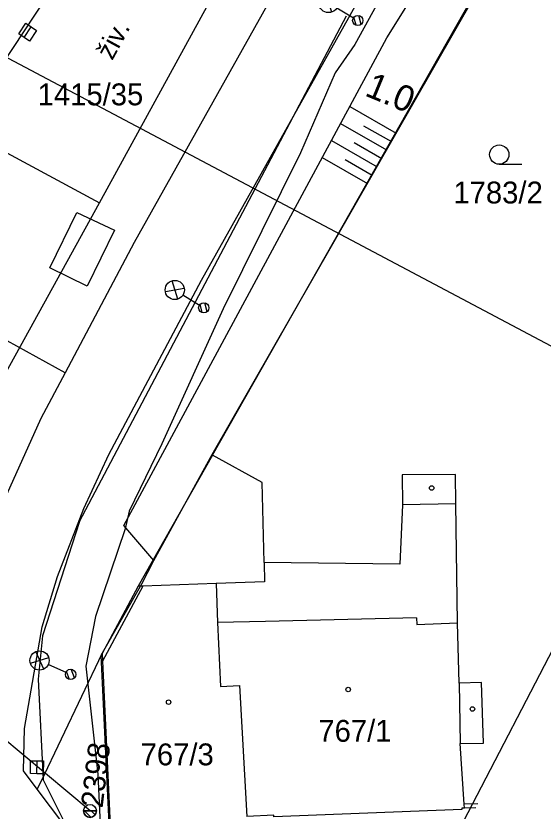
# Model space of a CAD drawing. Extents: x -781083 to -763634, y -1029516 to -1022695.
# Drawn here: x -765189.4 to -765148.4, y -1024336.1 to -1024274.3 of the extents above; entities that cross this region are included whole.
import ezdxf

# ---------------------------------------------------------------- set-up
doc = ezdxf.new("R2010")
doc.units = 0
for name, color, linetype in [('CETIN_nezaměřený', 7, 'Continuous'), ('Hranice parcel', 7, 'Continuous'), ('Parcelní čísla', 7, 'Continuous'), ('Vnitřní kresba', 7, 'Continuous'), ('Vrstva 16', 7, 'Continuous'), ('Vrstva 17', 7, 'Continuous'), ('Vrstva 23', 7, 'Continuous'), ('Vrstva 25', 7, 'Continuous'), ('Vrstva 36', 7, 'Continuous'), ('Vrstva 43', 7, 'Continuous'), ('Vrstva 48', 7, 'Continuous'), ('Vrstva 49', 7, 'Continuous'), ('Vrstva 5', 7, 'Continuous'), ('Vrstva 51', 7, 'Continuous'), ('Značky budov', 7, 'Continuous'), ('Značky kultur', 7, 'Continuous')]:
    doc.layers.add(name, color=color, linetype=linetype)

# ---------------------------------------------------------------- blocks, each defined once
blk = doc.blocks.new('4.02')
at = {"layer": 'Značky budov'}
blk.add_circle((-0.07, 0.01), 1.75, dxfattribs=at)
blk = doc.blocks.new('3.04')
at = {"layer": 'Značky kultur'}
blk.add_line((0.07, 0), (17.57, 0), dxfattribs=at)
blk.add_circle((0.07, 7.5), 7.5, dxfattribs=at)
blk = doc.blocks.new('C187_11')
at = {"layer": 'Vrstva 25'}
for p, q in [((-4.94, 32.07), (5, 20.95)), ((-4.79, 20.77), (5.05, 31.98)), ((0, 19), (0, 4)), ((-3.89, -0.8), (0.8, 3.89)), ((-1.21, -3.77), (3.79, 1.23))]:
    blk.add_line(p, q, dxfattribs=at)
for centre, radius in [((-0.03, 26.48), 7.49), ((0, 0), 4), ((0, 0), 4)]:
    blk.add_circle(centre, radius, dxfattribs=at)
blk = doc.blocks.new('C187_17')
at = {"layer": 'Vrstva 25'}
for p, q in [((-4.94, 32.07), (5, 20.95)), ((-4.79, 20.77), (5.05, 31.98)), ((0, 19), (0, 4)), ((-3.89, -0.8), (0.8, 3.89)), ((-1.21, -3.77), (3.79, 1.23))]:
    blk.add_line(p, q, dxfattribs=at)
for centre, radius in [((-0.03, 26.48), 7.49), ((0, 0), 4), ((0, 0), 4)]:
    blk.add_circle(centre, radius, dxfattribs=at)
blk = doc.blocks.new('C187_8')
at = {"layer": 'Vrstva 25'}
for p, q in [((-4.94, 32.07), (5, 20.95)), ((-4.79, 20.77), (5.05, 31.98)), ((0, 19), (0, 4)), ((-3.89, -0.8), (0.8, 3.89)), ((-1.21, -3.77), (3.79, 1.23))]:
    blk.add_line(p, q, dxfattribs=at)
for centre, radius in [((-0.03, 26.49), 7.49), ((0, 0), 4), ((0, 0), 4)]:
    blk.add_circle(centre, radius, dxfattribs=at)
blk = doc.blocks.new('C724_9')
at = {"layer": 'Vrstva 36'}
for p, q in [((-5.03, 0), (5.03, 0)), ((5.03, 0), (-5.03, 0)), ((0.63, -4.98), (-4.34, 0)), ((3.98, -3.02), (0.96, 0))]:
    blk.add_line(p, q, dxfattribs=at)
blk.add_lwpolyline([(-5.03, 0), (5.03, 0)], dxfattribs=at)
blk.add_circle((0, 0), 5.03, dxfattribs=at)
blk.add_arc((0, 0), 5.03, 180, 0, dxfattribs=at)
blk.add_arc((0, 0), 5.03, 180, 0, dxfattribs=at)
blk = doc.blocks.new('C154_1')
at = {"layer": 'Vrstva 43'}
blk.add_lwpolyline([(-5, 0), (-5, 5), (5, 5), (5, -5), (-5, -5), (-5, 0), (5, 0)], dxfattribs=at)

msp = doc.modelspace()

# ---------------------------------------------------------------- linework, layer by layer
msp.add_lwpolyline([(-765336.117, -1024363.479), (-765204.05, -1024432.093), (-764769.725, -1023596.107), (-764901.792, -1023527.494)], close=True)
at = {"layer": 'CETIN_nezaměřený'}
msp.add_lwpolyline([(-765156.32, -1024264.33), (-765163.03, -1024276.53), (-765164.57, -1024278.73), (-765167.26, -1024284.94), (-765173.26, -1024297.07), (-765178.03, -1024307.57), (-765180.58, -1024312.81), (-765180.89, -1024314.18), (-765183.19, -1024320.98), (-765183.94, -1024324.85), (-765183.02, -1024333.24), (-765182.82, -1024337.72)], dxfattribs=at)
at = {"layer": 'Hranice parcel'}
for p, q in [((-765174.11, -1024308.46), (-765144.5, -1024256.37)), ((-765185.57, -1024302.05), (-765199.67, -1024294.27)), ((-765185.67, -1024337.15), (-765187.73, -1024334.42)), ((-765153.624, -1024335.86), (-765154.51, -1024335.89))]:
    msp.add_line(p, q, dxfattribs=at)
for points in [[(-765187.73, -1024334.42), (-765188.8, -1024333), (-765188.73, -1024329.7), (-765187.34, -1024321.79), (-765186.15, -1024317.88), (-765184.1, -1024312.59), (-765182.16, -1024308.4), (-765174.96, -1024294.85), (-765154.33, -1024258.05), (-765087.21, -1024139.28), (-765076.299, -1024121.401)], [(-765155.36, -1024247.61), (-765159.55, -1024255.1), (-765180.19, -1024291.92), (-765185.57, -1024302.05)], [(-765185.57, -1024302.05), (-765187.45, -1024305.59), (-765201.77, -1024337.33), (-765206.13, -1024339.71), (-765227.39, -1024341.18)], [(-765174.11, -1024308.46), (-765179.87, -1024318.64), (-765182.68, -1024323.87)], [(-765170.09, -1024316.78), (-765170.24, -1024310.58), (-765174.11, -1024308.46)], [(-765154.51, -1024335.89), (-765154.53, -1024335.59), (-765154.83, -1024330.87), (-765153.03, -1024330.83), (-765153.19, -1024326.13), (-765154.93, -1024326.17), (-765155.04, -1024321.48), (-765155.19, -1024312.22), (-765155.21, -1024309.96), (-765159.36, -1024309.99), (-765159.33, -1024312.3), (-765159.54, -1024316.93), (-765170.09, -1024316.78)], [(-765170.09, -1024316.78), (-765170.05, -1024318.3), (-765173.81, -1024318.43), (-765173.71, -1024321.46), (-765173.47, -1024326.42), (-765172, -1024326.35), (-765171.43, -1024336.53)], [(-765187.73, -1024334.42), (-765187.42, -1024333.82), (-765182.68, -1024323.87)], [(-765182.68, -1024323.87), (-765182.65, -1024324.45), (-765182.09, -1024336.66), (-765182.08, -1024336.96)], [(-765154.51, -1024335.89), (-765154.71, -1024335.89), (-765154.71, -1024336), (-765169.33, -1024336.57), (-765169.33, -1024336.44), (-765171.43, -1024336.53)]]:
    msp.add_lwpolyline(points, dxfattribs=at)
at = {"layer": 'Vnitřní kresba'}
for p, q in [((-765186.75, -1024293.88), (-765184.65, -1024289.58)), ((-765184.65, -1024289.58), (-765181.72, -1024290.95)), ((-765181.72, -1024290.95), (-765183.85, -1024295.3)), ((-765183.85, -1024295.3), (-765186.75, -1024293.88)), ((-765155.19, -1024312.22), (-765159.33, -1024312.3)), ((-765179.52, -1024318.63), (-765182.65, -1024324.45)), ((-765179.52, -1024318.63), (-765179.87, -1024318.64)), ((-765173.81, -1024318.43), (-765179.52, -1024318.63)), ((-765169.98, -1024321.37), (-765173.71, -1024321.46)), ((-765158.24, -1024321.09), (-765169.98, -1024321.37)), ((-765158.24, -1024321.09), (-765158.22, -1024321.6)), ((-765158.22, -1024321.6), (-765155.04, -1024321.48)), ((-765154.93, -1024326.17), (-765154.83, -1024330.87)), ((-765153.465, -1024335.555), (-765154.53, -1024335.59))]:
    msp.add_line(p, q, dxfattribs=at)
at = {"layer": 'Vrstva 16'}
for points in [[(-765196.139, -1024281.778), (-765193.738, -1024283.002), (-765180.473, -1024262.935), (-765183.248, -1024261.22), (-765196.139, -1024281.778)], [(-765193.738, -1024283.002), (-765182.878, -1024288.822)]]:
    msp.add_lwpolyline(points, dxfattribs=at)
at = {"layer": 'Vrstva 17'}
for points in [[(-765174.12, -1024308.406), (-765144.238, -1024256.217)], [(-765182.132, -1024337.077), (-765182.772, -1024323.992), (-765179.61, -1024318.44), (-765178.654, -1024316.64)]]:
    msp.add_lwpolyline(points, dxfattribs=at)
at = {"layer": 'Vrstva 23'}
msp.add_lwpolyline([(-765178.654, -1024316.64), (-765174.12, -1024308.406)], dxfattribs=at)
at = {"layer": 'Vrstva 25'}
msp.add_lwpolyline([(-765183.627, -1024336.105), (-765209.691, -1024314.336)], dxfattribs=at)
at = {"layer": 'Vrstva 48'}
for p, q in [((-765163.431, -1024281.351), (-765159.814, -1024283.421)), ((-765164.143, -1024282.672), (-765160.56, -1024284.723)), ((-765162.347, -1024282.836), (-765160.187, -1024284.072)), ((-765164.854, -1024283.992), (-765161.305, -1024286.025)), ((-765163.072, -1024284.149), (-765160.932, -1024285.374)), ((-765165.566, -1024285.313), (-765162.05, -1024287.326)), ((-765163.797, -1024285.462), (-765161.678, -1024286.675))]:
    msp.add_line(p, q, dxfattribs=at)
at = {"layer": 'Vrstva 49'}
for points in [[(-765174.12, -1024308.406), (-765144.238, -1024256.217), (-765126.49, -1024224.567), (-765128.139, -1024221.83), (-765124.809, -1024214.48)], [(-765160.543, -1024275.992), (-765145.719, -1024252.299), (-765133.555, -1024229.635), (-765124.809, -1024214.48)], [(-765178.654, -1024316.64), (-765180.986, -1024313.926), (-765160.543, -1024275.992)]]:
    msp.add_lwpolyline(points, dxfattribs=at)
at = {"layer": 'Vrstva 5'}
msp.add_line((-765204.077, -1024270.142), (-765137.727, -1024305.261), dxfattribs=at)
at = {"layer": 'Vrstva 51'}
for points in [[(-765182.878, -1024288.822), (-765173.205, -1024271.109)], [(-765184.451, -1024313.612), (-765163.691, -1024274.3)], [(-765237.237, -1024342.164), (-765229.818, -1024342.411), (-765204.257, -1024340.379), (-765202.415, -1024339.482), (-765201.543, -1024337.639), (-765197.493, -1024320.94), (-765190.15, -1024301.998), (-765182.878, -1024288.822)], [(-765184.451, -1024313.612), (-765187.32, -1024322.493), (-765187.672, -1024325.855), (-765187.276, -1024333.693), (-765185.503, -1024337.203)]]:
    msp.add_lwpolyline(points, dxfattribs=at)

# ---------------------------------------------------------------- block references
at = {"layer": 'Vrstva 25'}
for name, p, xscale, yscale, rotation in [('C187_11', (-765162.806, -1024274.658), 0.09999999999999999, 0.09999999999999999, 59.0430811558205), ('C187_17', (-765174.78, -1024296.993), 0.09999999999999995, 0.09999999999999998, 58.36201174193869), ('C187_8', (-765185.134, -1024325.491), 0.09999999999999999, 0.1, 65.812542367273)]:
    msp.add_blockref(name, p, dxfattribs=dict(at, xscale=xscale, yscale=yscale, rotation=rotation))
at = {"layer": 'Vrstva 36', "xscale": 0.1, "yscale": 0.10000000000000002}
msp.add_blockref('C724_9', (-765183.627, -1024336.105), dxfattribs=at)
at = {"layer": 'Vrstva 43', "xscale": 0.09999999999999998}
for p, yscale, rotation in [((-765188.483, -1024275.564), 0.09999999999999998, 56.53392652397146), ((-765187.755, -1024332.711), 0.1, 89.45757695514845)]:
    msp.add_blockref('C154_1', p, dxfattribs=dict(at, yscale=yscale, rotation=rotation))
at = {"layer": 'Značky budov', "xscale": 0.1, "yscale": 0.10000000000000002}
for p in [(-765157.05, -1024311), (-765163.54, -1024326.67), (-765177.51, -1024327.65), (-765153.88, -1024328.18)]:
    msp.add_blockref('4.02', p, dxfattribs=at)
at = {"layer": 'Značky kultur', "xscale": 0.1, "yscale": 0.10000000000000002}
msp.add_blockref('3.04', (-765151.81, -1024285.83), dxfattribs=at)

# ---------------------------------------------------------------- texts
at = {"layer": 'Parcelní čísla'}
for s, p in [('1415/35', (-765187.702, -1024281.25)), ('1783/2', (-765155.37, -1024288.88)), ('767/1', (-765165.87, -1024330.73)), ('767/3', (-765179.69, -1024332.56))]:
    msp.add_text(s, height=1.7, dxfattribs=at).set_placement(p)
msp.add_text('2398', height=1.7, rotation=83, dxfattribs=at).set_placement((-765182.656, -1024335.923))
at = {"layer": 'Vrstva 48'}
msp.add_text('1.0', height=2, rotation=337.60629, dxfattribs=at).set_placement((-765162.339, -1024280.467))
at = {"layer": 'Vrstva 51'}
msp.add_text('živ.', height=1.5, rotation=61.36122, dxfattribs=at).set_placement((-765181.9, -1024277.812))

doc.saveas('drawing.dxf')
